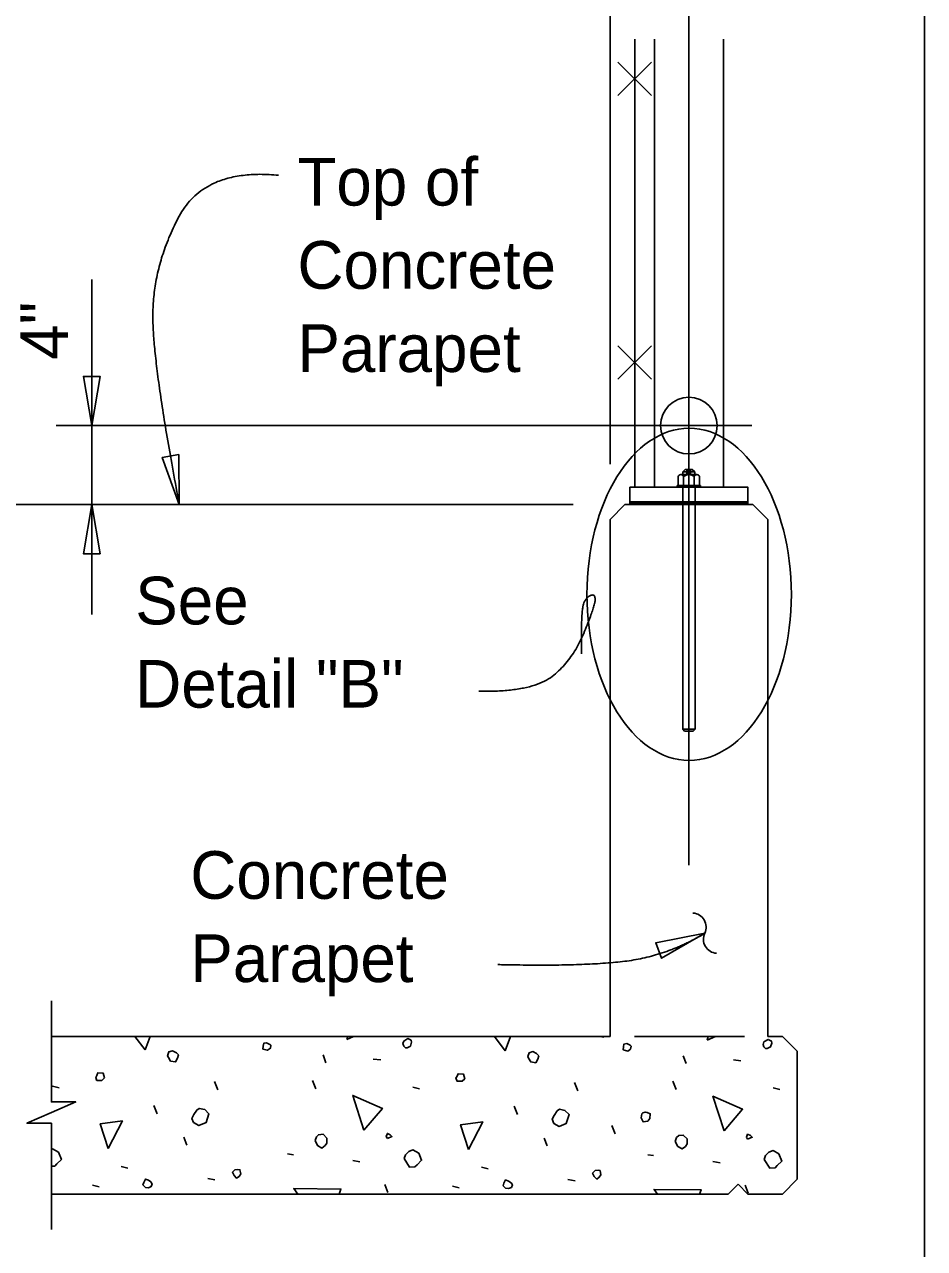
# Model space of a CAD drawing. Extents: x 0 to 41.1, y 0 to 25.9.
# Drawn here: x 37.24 to 41.05, y 13.66 to 18.84 of the extents above; entities that cross this region are included whole.
import ezdxf

# ---------------------------------------------------------------- set-up
doc = ezdxf.new("R2010")
doc.units = 0
for name, color, linetype in [('ActivePts-ConstElements', 7, 'Continuous'), ('CL_Major', 7, 'Continuous'), ('Dimension', 7, 'Continuous'), ('Miscellaneous', 7, 'Continuous'), ('Miscellaneous1', 7, 'Continuous'), ('SteelMisc', 7, 'Continuous'), ('SteelMisc_h', 7, 'Continuous'), ('SupstrConc', 7, 'Continuous'), ('SupstrConc_h', 7, 'Continuous'), ('TextStructures', 7, 'Continuous')]:
    doc.layers.add(name, color=color, linetype=linetype)

msp = doc.modelspace()

# ---------------------------------------------------------------- linework, layer by layer
at = {"layer": 'ActivePts-ConstElements'}
msp.add_lwpolyline([(0, 0), (41.0506, 0), (41.0506, 25.9461), (0, 25.9461)], close=True, dxfattribs=at)
msp.add_lwpolyline([(0, 0), (41.0506, 0), (41.0506, 25.9461), (0, 25.9461)], close=True, dxfattribs=at)
msp.add_lwpolyline([(0, 0), (41.0506, 0), (41.0506, 25.9461), (0, 25.9461)], close=True, dxfattribs=at)
at = {"layer": 'CL_Major'}
for p, q in [((40.0537, 15.2829), (40.0537, 19.5023)), ((37.3776, 17.1412), (40.3194, 17.1412))]:
    msp.add_line(p, q, dxfattribs=at)
at = {"layer": 'Dimension'}
for p, q in [((39.7204, 16.9785), (39.7204, 19.0859)), ((37.5276, 16.3425), (37.5276, 17.7595)), ((40.0537, 16.8885), (40.0537, 16.8878)), ((39.5643, 16.8079), (36.8659, 16.8079))]:
    msp.add_line(p, q, dxfattribs=at)
for points in [[(37.5276, 17.1412), (37.5629, 17.3494), (37.4923, 17.3494)], [(37.8983, 16.8079), (37.8958, 17.0191), (37.8263, 17.0065)], [(37.5276, 16.8079), (37.4923, 16.5997), (37.5629, 16.5997)], [(40.1214, 14.994), (39.9139, 14.9544), (39.9386, 14.8883)]]:
    msp.add_lwpolyline(points, close=True, dxfattribs=at)
msp.add_lwpolyline([(37.3569, 14.7079), (37.3569, 14.2808), (37.4602, 14.2808), (37.3569, 14.2358), (37.2536, 14.1908), (37.3569, 14.1908), (37.3569, 13.7412)], dxfattribs=at)
for centre, start, end in [((40.0672, 15.0202), 334.6162, 86.3434), ((40.1749, 14.9691), 154.6162, 266.3434)]:
    msp.add_arc(centre, 0.0596, start, end, dxfattribs=at)
msp.add_ellipse((40.055, 16.4277), major_axis=(0, 0.7024), ratio=0.61552, dxfattribs=at)
for points in [[(38.3183, 18.2002), (38.0045, 18.2308), (37.7862, 17.8152), (37.7862, 17.3959), (37.8983, 16.8079)], [(39.1649, 16.0179), (39.3915, 16.0139), (39.562, 16.1489), (39.6571, 16.379), (39.6571, 16.4308), (39.6199, 16.4159), (39.5976, 16.3632), (39.599, 16.1763)], [(39.246, 14.8617), (39.5846, 14.8535), (39.9562, 14.8948), (40.1214, 14.994)]]:
    msp.add_open_spline(points, degree=2, dxfattribs=at)
at = {"layer": 'Miscellaneous'}
for p, q in [((39.8952, 18.6785), (39.7538, 18.5373)), ((39.7538, 18.6785), (39.8952, 18.5373)), ((39.8952, 17.4785), (39.7538, 17.3373)), ((39.7538, 17.4785), (39.8952, 17.3373)), ((40.0425, 16.9502), (40.0633, 16.9502)), ((40.0425, 16.9405), (40.0633, 16.9405)), ((39.8037, 16.8148), (40.3037, 16.8148)), ((39.8037, 16.8113), (40.3037, 16.8113)), ((38.169, 14.5579), (38.1703, 14.5576)), ((39.6751, 14.5579), (39.6941, 14.5541)), ((38.5186, 14.4462), (38.5062, 14.4798)), ((38.7183, 14.4622), (38.7501, 14.4586)), ((40.0424, 14.4427), (40.03, 14.4763)), ((40.2421, 14.4586), (40.274, 14.4551)), ((37.3624, 14.3473), (37.3907, 14.3402)), ((38.0607, 14.3313), (38.0466, 14.3667)), ((38.4761, 14.3366), (38.462, 14.372)), ((38.8863, 14.3437), (38.9145, 14.3366)), ((39.5845, 14.3278), (39.5704, 14.3632)), ((39.9999, 14.3331), (39.9858, 14.3685)), ((40.4101, 14.3402), (40.4384, 14.3331)), ((37.8044, 14.2306), (37.7902, 14.2659)), ((39.3282, 14.227), (39.3141, 14.2624)), ((39.7419, 14.1457), (39.7277, 14.1811)), ((37.9299, 14.098), (37.9175, 14.1316)), ((39.4537, 14.0945), (39.4413, 14.128)), ((38.3559, 14.0609), (38.3807, 14.0573)), ((38.6317, 14.0326), (38.6617, 14.0273)), ((39.8797, 14.0573), (39.9045, 14.0538)), ((37.6524, 14.0078), (37.6806, 14.0008)), ((39.1762, 14.0043), (39.2045, 13.9972)), ((40.1555, 14.0291), (40.1856, 14.0238)), ((37.5304, 13.9283), (37.5587, 13.9212)), ((38.0183, 13.9566), (38.0483, 13.9513)), ((38.7802, 13.8982), (38.7678, 13.9318)), ((39.5421, 13.953), (39.5721, 13.9477)), ((40.304, 13.8947), (40.2916, 13.9283)), ((39.0542, 13.9248), (39.0825, 13.9177))]:
    msp.add_line(p, q, dxfattribs=at)
for points in [[(39.8246, 18.7753), (39.8246, 16.8808)], [(37.7531, 14.501), (37.7099, 14.5579)], [(37.7744, 14.5579), (37.7531, 14.501)], [(38.6069, 14.5452), (38.6108, 14.5579)], [(38.6351, 14.5579), (38.6069, 14.5452)], [(38.8544, 14.5099), (38.8615, 14.5099), (38.8756, 14.517), (38.881, 14.5329), (38.8792, 14.5417), (38.865, 14.5488), (38.8474, 14.5382), (38.8438, 14.5276), (38.8474, 14.517), (38.8544, 14.5099)], [(39.2769, 14.4975), (39.231, 14.5579)], [(39.2995, 14.5579), (39.2769, 14.4975)], [(40.1308, 14.5417), (40.1357, 14.5579)], [(40.1668, 14.5579), (40.1308, 14.5417)], [(37.3569, 14.5357), (37.3571, 14.5364), (37.3569, 14.5376)], [(37.8521, 14.4692), (37.861, 14.4533), (37.8822, 14.4498), (37.891, 14.4657), (37.8945, 14.4798), (37.8857, 14.4887), (37.8698, 14.4975), (37.8539, 14.4922), (37.8486, 14.4763), (37.8521, 14.4692)], [(38.2516, 14.5046), (38.2711, 14.4993), (38.2834, 14.5081), (38.2852, 14.5205), (38.2817, 14.524), (38.2675, 14.5311), (38.2552, 14.5293), (38.2534, 14.517), (38.2516, 14.5046)], [(39.7754, 14.501), (39.7949, 14.4957), (39.8073, 14.5046), (39.809, 14.517), (39.8055, 14.5205), (39.7914, 14.5276), (39.779, 14.5258), (39.7772, 14.5134), (39.7754, 14.501)], [(40.3782, 14.5064), (40.3853, 14.5064), (40.3995, 14.5134), (40.4048, 14.5293), (40.403, 14.5382), (40.3889, 14.5452), (40.3712, 14.5346), (40.3676, 14.524), (40.3712, 14.5134), (40.3782, 14.5064)], [(39.3759, 14.4657), (39.3848, 14.4498), (39.406, 14.4462), (39.4148, 14.4622), (39.4184, 14.4763), (39.4095, 14.4851), (39.3936, 14.494), (39.3777, 14.4887), (39.3724, 14.4728), (39.3759, 14.4657)], [(37.5498, 14.372), (37.571, 14.372), (37.5816, 14.3826), (37.5763, 14.4021), (37.5534, 14.4038), (37.5498, 14.3932), (37.5445, 14.3844), (37.5498, 14.372), (37.5463, 14.3755)], [(39.0736, 14.3685), (39.0949, 14.3685), (39.1055, 14.3791), (39.1002, 14.3985), (39.0772, 14.4003), (39.0736, 14.3897), (39.0683, 14.3808), (39.0736, 14.3685), (39.0701, 14.372)], [(38.6794, 14.1616), (38.6317, 14.3084), (38.7572, 14.2536), (38.6794, 14.1616)], [(40.2032, 14.1581), (40.1555, 14.3048), (40.281, 14.25), (40.2032, 14.1581)], [(37.9582, 14.1935), (37.9812, 14.1811), (38.0112, 14.1935), (38.0236, 14.2306), (38.0059, 14.2483), (37.9829, 14.2536), (37.9723, 14.2465), (37.9599, 14.227), (37.9511, 14.2111), (37.9582, 14.1935)], [(39.482, 14.1899), (39.505, 14.1775), (39.535, 14.1899), (39.5474, 14.227), (39.5297, 14.2447), (39.5067, 14.25), (39.4961, 14.243), (39.4838, 14.2235), (39.4749, 14.2076), (39.482, 14.1899)], [(39.8515, 14.2129), (39.8603, 14.197), (39.8797, 14.1988), (39.8886, 14.2111), (39.8903, 14.2306), (39.878, 14.2359), (39.8691, 14.2377), (39.8585, 14.2341), (39.855, 14.2306), (39.8515, 14.2129)], [(37.5976, 14.0839), (37.564, 14.1882), (37.6577, 14.2005), (37.5976, 14.0839)], [(39.1214, 14.0803), (39.0878, 14.1846), (39.1815, 14.197), (39.1214, 14.0803)], [(38.4726, 14.1174), (38.4832, 14.0962), (38.5009, 14.0856), (38.515, 14.0962), (38.5221, 14.1068), (38.5221, 14.128), (38.5062, 14.144), (38.4867, 14.1422), (38.4779, 14.1334), (38.4726, 14.1174)], [(38.7784, 14.1263), (38.7979, 14.1351), (38.7908, 14.1422), (38.7784, 14.1475), (38.7731, 14.1351), (38.7784, 14.1263)], [(39.9964, 14.1139), (40.007, 14.0927), (40.0247, 14.0821), (40.0388, 14.0927), (40.0459, 14.1033), (40.0459, 14.1245), (40.03, 14.1404), (40.0106, 14.1387), (40.0017, 14.1298), (39.9964, 14.1139)], [(40.3022, 14.1227), (40.3217, 14.1316), (40.3146, 14.1387), (40.3022, 14.144), (40.2969, 14.1316), (40.3022, 14.1227)], [(37.3569, 14.0085), (37.3713, 14.0096), (37.3801, 14.0184), (37.3996, 14.0379), (37.3872, 14.0679), (37.3624, 14.0821), (37.3569, 14.0799)], [(38.8491, 14.0414), (38.8721, 14.0043), (38.8951, 14.0061), (38.9039, 14.0149), (38.9234, 14.0344), (38.911, 14.0644), (38.8863, 14.0786), (38.8686, 14.0715), (38.8544, 14.0573), (38.8491, 14.0414)], [(40.3729, 14.0379), (40.3959, 14.0008), (40.4189, 14.0025), (40.4277, 14.0114), (40.4472, 14.0308), (40.4348, 14.0609), (40.4101, 14.075), (40.3924, 14.0679), (40.3782, 14.0538), (40.3729, 14.0379)], [(38.1297, 13.969), (38.1403, 13.9583), (38.1509, 13.9654), (38.1579, 13.976), (38.1544, 13.9937), (38.1456, 13.9955), (38.1332, 13.9937), (38.1226, 13.9831), (38.1297, 13.969)], [(39.6535, 13.9654), (39.6641, 13.9548), (39.6747, 13.9619), (39.6817, 13.9725), (39.6782, 13.9902), (39.6694, 13.9919), (39.657, 13.9902), (39.6464, 13.9796), (39.6535, 13.9654)], [(37.7549, 13.9195), (37.7673, 13.9177), (37.7796, 13.923), (37.7832, 13.9336), (37.7779, 13.9424), (37.7673, 13.9495), (37.7549, 13.9548), (37.7478, 13.9407), (37.7443, 13.9301), (37.7549, 13.9195)], [(39.2787, 13.9159), (39.2911, 13.9142), (39.3034, 13.9195), (39.307, 13.9301), (39.3017, 13.9389), (39.2911, 13.946), (39.2787, 13.9513), (39.2716, 13.9371), (39.2681, 13.9265), (39.2787, 13.9159)], [(38.3999, 13.8912), (38.3824, 13.9142), (38.5822, 13.9124), (38.5743, 13.8912)], [(39.921, 13.8912), (39.9063, 13.9106), (40.106, 13.9088), (40.0994, 13.8912)]]:
    msp.add_lwpolyline(points, dxfattribs=at)
msp.add_lwpolyline([(39.8037, 16.8183), (40.3037, 16.8183), (40.3037, 16.8079), (39.8037, 16.8079)], close=True, dxfattribs=at)
at = {"layer": 'Miscellaneous1'}
msp.add_lwpolyline([(0, 25.9461), (41.0506, 25.9461), (41.0506, 0), (0, 0)], close=True, dxfattribs=at)
at = {"layer": 'SteelMisc'}
for p, q in [((39.9079, 16.8808), (39.9079, 18.7753)), ((40.1996, 16.8808), (40.1996, 18.7753)), ((40.0878, 16.9342), (40.0197, 16.9342)), ((40.0376, 16.9551), (40.028, 16.9454)), ((40.028, 16.9454), (40.028, 16.9342)), ((40.028, 16.9454), (40.0795, 16.9454)), ((40.0376, 16.9551), (40.0682, 16.9551)), ((40.0682, 16.9551), (40.0795, 16.9454)), ((40.0795, 16.9454), (40.0795, 16.9342)), ((40.0041, 16.8878), (40.0041, 16.8807)), ((40.0041, 16.8878), (40.1035, 16.8878)), ((40.0083, 16.9255), (40.0083, 16.8878)), ((40.0991, 16.8878), (40.0083, 16.8878)), ((40.031, 16.9257), (40.031, 16.8878)), ((40.0764, 16.9257), (40.0764, 16.8878)), ((40.0991, 16.9255), (40.0991, 16.8878)), ((40.1035, 16.8878), (40.1035, 16.8807)), ((39.9339, 16.8183), (40.1735, 16.8183))]:
    msp.add_line(p, q, dxfattribs=at)
msp.add_lwpolyline([(39.8037, 16.8808), (40.3037, 16.8808), (40.3037, 16.8183), (39.8037, 16.8183)], close=True, dxfattribs=at)
msp.add_circle((40.0537, 17.1412), 0.1198, dxfattribs=at)
for centre, radius, start, end in [((40.0197, 16.9224), 0.0118, 16.5986, 164.7005), ((40.0537, 16.8994), 0.0347, 49.2015, 130.7985), ((40.0877, 16.9224), 0.0118, 15.1506, 163.5042)]:
    msp.add_arc(centre, radius, start, end, dxfattribs=at)
at = {"layer": 'SteelMisc_h'}
for p, q in [((40.0277, 16.8808), (40.0277, 15.8576)), ((40.0798, 16.8808), (40.0798, 15.8576)), ((40.0277, 15.8576), (40.0798, 15.8576)), ((40.0277, 15.8576), (40.0359, 15.8495)), ((40.0359, 15.8495), (40.0716, 15.8495)), ((40.0798, 15.8576), (40.0716, 15.8495))]:
    msp.add_line(p, q, dxfattribs=at)
at = {"layer": 'SupstrConc'}
for p, q in [((39.7829, 16.8079), (39.7204, 16.7445)), ((40.3245, 16.8079), (39.7829, 16.8079)), ((40.3245, 16.8079), (40.3871, 16.7445)), ((39.7204, 14.5579), (39.7204, 16.7445)), ((40.3871, 14.5579), (40.3871, 16.7445)), ((37.3569, 14.5579), (39.7204, 14.5579)), ((40.3871, 14.5579), (40.4496, 14.5579)), ((40.4496, 14.5579), (40.5121, 14.4954)), ((40.5121, 14.4954), (40.5121, 13.9537)), ((40.2204, 13.8912), (40.2621, 13.9329)), ((40.2621, 13.9329), (40.3037, 13.8912)), ((40.5121, 13.9537), (40.4496, 13.8912)), ((40.2204, 13.8912), (37.3569, 13.8912)), ((40.4496, 13.8912), (40.3037, 13.8912))]:
    msp.add_line(p, q, dxfattribs=at)
at = {"layer": 'SupstrConc_h'}
msp.add_line((40.2885, 14.5579), (39.8234, 14.5579), dxfattribs=at)

# ---------------------------------------------------------------- texts
at = {"layer": 'Dimension'}
for s, p in [('Top of ', (38.3979, 18.0721)), ('Concrete', (38.3979, 17.7201)), ('Parapet', (38.3979, 17.3681)), ('See ', (37.7119, 16.3006)), ('Detail "B"', (37.7119, 15.9486)), ('Concrete', (37.9448, 15.1398)), ('Parapet', (37.9448, 14.7878))]:
    msp.add_text(s, height=0.2016, dxfattribs=at).set_placement(p)
at = {"layer": 'TextStructures'}
msp.add_text('4"', height=0.2016, rotation=90, dxfattribs=at).set_placement((37.4279, 17.4197))

doc.saveas('drawing.dxf')
